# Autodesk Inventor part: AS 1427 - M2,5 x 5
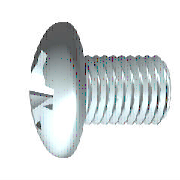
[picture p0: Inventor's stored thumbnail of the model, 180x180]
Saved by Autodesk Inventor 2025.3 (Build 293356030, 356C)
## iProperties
Created: 2024-01
Part Number: AS 1427 - M2,5 x 5
Material: Acciaio, Dolce
Description: Phillips Viti metriche ISO
Document SubType Name: Modeling
Standard: AS 1427
Designer: R5800u
Standards Organization: AS
Language: it-IT
Size Designation: M2,5 x 5
Categories: <MemberInstance><Categories><Category DisplayName="Elementi di fissaggio" InternalName="e4da775c-781d-43d5-af7c-5136215cf5a6" Mnemonic="FSTN"><Category DisplayN
Density: 7.85 g/cm^3
Appearance: Semilucidato
IsCustomPart: 0
Author: R5800u
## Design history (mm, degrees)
body "Solid1"
workplane "Work Plane3"
sketch "Schizzo4"
  geometry: L1 (-9, 0)-(9, 0) reference; L2 (0, -9)-(0, 9) reference; L3 (0, 0)-(6.428, 6.428); L4 (0, 0)-(6.428, -6.428); L5 (0, 0)-(-6.428, 6.428); L6 (0, 0)-(-6.428, -6.428); L7 (0.94, 0.94)-(0, 0.128); L8 (-0.94, 0.94)-(-0.128, 0); L9 (-0.94, -0.94)-(0, -0.128); L10 (0.94, -0.94)-(0.127, 0); L11 (0.94, 0.94)-(0.128, 0); L12 (-0.94, 0.94)-(0, 0.128); L13 (-0.94, -0.94)-(-0.127, 0); L14 (0.94, -0.94)-(0, -0.128); C1 r 2.5 at (0, 0) reference; A1 r 0.128 centre (0, 0) between (0, 0.128) and (-0.128, 0); A2 r 1.33 centre (0, 0) between (0.94, 0.94) and (0.94, -0.94); 1 further point
  constraints: 24 end point, 10 point on line, 7 point on circle, 3 perpendicular, 3 symmetric about line, 2 centre point, 2 coincident, 3 other
  dimensions: "d11" = 0.255 diameter of A1 (= 0.5 x SBR); "d14" = 45 deg angle of L3 L1; "d35" = 0.94045 distance from line of L1 L7.start (= 0.353553 x SDM)
extrude "Taglio a stella" cut sketch "Schizzo4" distance "d12" = 1.75 (= KOH); taper "d13" = -10 deg
sketch "Schizzo2"
  geometry: L1 (-4.344, 0)-(8.565, 0) reference; L2 (0, -4.344)-(0, 8.565) reference; L3 (0, 1.33)-(0, 0); L4 (0, 0)-(1.33, 0); L5 (0, 0)-(6.721, 6.721); L6 (0.255, 1.305)-(0.176, 0.641); L7 (1.305, 0.255)-(0.641, 0.176); L8 (1.305, -0.255)-(0.641, -0.176); L9 (0.255, -1.305)-(0.176, -0.641); L10 (-0.255, 1.305)-(-0.176, 0.641); L11 (-1.305, 0.255)-(-0.641, 0.176); L12 (-0.255, -1.305)-(-0.176, -0.641); L13 (-1.305, -0.255)-(-0.641, -0.176); C1 r 2.5 at (0, 0) reference; A1 r 0.532 centre (0, 0) between (0.532, 0) and (0, 0.532); A2 r 0.184 centre (0.359, 0.62) between (0.176, 0.641) and (0.489, 0.489); A3 r 0.184 centre (0.62, 0.359) between (0.489, 0.489) and (0.641, 0.176); A4 r 1.33 centre (0, 0) between (1.33, 0) and (1.305, 0.255); A5 r 1.33 centre (0, 0) between (0.255, 1.305) and (0, 1.33); A6 r 1.33 centre (0, 0) between (1.305, 0.255) and (0.255, 1.305); A7 r 1.33 centre (0, 0) between (0, -1.33) and (0.255, -1.305); A8 r 1.33 centre (0, 0) between (0.255, -1.305) and (1.305, -0.255); A9 r 1.33 centre (0, 0) between (1.305, -0.255) and (1.33, 0); A10 r 0.184 centre (0.359, -0.62) between (0.489, -0.489) and (0.176, -0.641); A11 r 0.184 centre (0.62, -0.359) between (0.641, -0.176) and (0.489, -0.489); A12 r 0.184 centre (-0.359, 0.62) between (-0.489, 0.489) and (-0.176, 0.641); A13 r 0.184 centre (-0.62, 0.359) between (-0.641, 0.176) and (-0.489, 0.489); A14 r 1.33 centre (0, 0) between (-1.305, 0.255) and (-1.33, 0); A15 r 1.33 centre (0, 0) between (-0.255, 1.305) and (-1.305, 0.255); A16 r 1.33 centre (0, 0) between (0, 1.33) and (-0.255, 1.305); A17 r 1.33 centre (0, 0) between (-1.33, 0) and (-1.305, -0.255); A18 r 1.33 centre (0, 0) between (-1.305, -0.255) and (-0.255, -1.305); A19 r 1.33 centre (0, 0) between (-0.255, -1.305) and (0, -1.33); A20 r 0.184 centre (-0.62, -0.359) between (-0.489, -0.489) and (-0.641, -0.176); A21 r 0.184 centre (-0.359, -0.62) between (-0.176, -0.641) and (-0.489, -0.489); A22 r 0.665 centre (0, 0) between (0.665, 0) and (0, 0.665)
  constraints: 46 point on circle, 25 symmetric about line, 22 centre point, 22 end point, 6 tangent, 4 coincident, 3 collinear, 3 point on line, 1 midpoint, 1 perpendicular, 22 other
  dimensions: "d4" = 45 deg angle of L5 L4; "d5" = 1.064 diameter of A1 (= 0.4 x SDM); "d6" = 2.66 diameter of A6 (= SDM); "d7" = 0.255 distance from line of L6.start L3 (= 0.5 x SBR); "d20" = 1.33 diameter of A22 (= 0.5 x SDM)
extrude "Intaglio" join sketch "Schizzo2" taper "d21" = 5 deg; stored distance "d54" = 10
revolve "Taglio" stored, may be unused: angle "d56" = 90 deg
revolve "Corpo" stored, may be unused: angle "d18" = 90 deg
workplane "Work Plane1"
sketch "Schizzo1"
  geometry: L1 (5, 0)-(5, 1.25); L2 (5, 1.25)-(0.9, 1.25); L3 (3.962, 5.08)-(3.962, 5.08); L4 (-1.75, 0)-(-1.75, 2.5); L5 (-1.521, 1.216)-(-1.229, 1.07); L6 (-1.229, 1.07)-(-0.66, 0); L7 (-0.66, 0)-(5, 0); L8 (-3.421, 0)-(6.403, 0) reference; L9 (0, -1.016)-(0, 6.096) reference; L10 (-1.521, 1.216)-(-1.75, 1.33); L11 (-0.63, 2.5)-(-1.75, 2.5); L12 (-0.63, 2.5)-(0, 2.5); L13 (0, 2.5)-(0, 1.112); L14 (0, 1.112)-(0.624, 1.112); L15 (0.624, 1.112)-(0.9, 1.25); L16 (0.9, 1.25)-(0, 1.25); A1 r 3.35 centre (1.6, 0) between (-0.63, 2.5) and (-1.75, 0)
  constraints: 28 end point, 5 point on line, 4 collinear, 4 point on circle, 3 parallel, 2 perpendicular, 1 centre point, 1 horizontal, 1 tangent
  dimensions: "d1" = 2.5 diameter of L2 L7 (= GD); "d2" = 1.09 distance from line of L6.end L4 (= STI); "d16" = 2.66 diameter of L10.end L7 (= SDM); "d17" = 62 deg angle of L6 L7; "d19" = 26.5 deg angle of L5 L7; "d23" = 5 diameter of L12.end L7 (= KOD); "d24" = 0.01 deg angle of L12 L7 (= KEWI); "d25" = 1.75 distance between parallel lines of L4 L13 (= KOH); "d26" = 3.35 radius of A1 (= KR); "d28" = 2.224 diameter of L14 L7 (= BDM); "d29" = 4.1 distance of L1.end L2.end (= GEL); "d30" = 0.27605 horizontal distance of L14.end L2.end (= GAL); "d31" = 5 distance between parallel lines of L13 L1 (= NLG)
fillet "Raccordo1" dims "d32" = 1 (= RR)
fillet "Raccordo2" dims "d22" = 0.102 (= 0.2 x SBR)
feature "Filettatura" dims "d8" = 4.1 (= GEL), "d9" = 0
chamfer "Smusso1" distance "d36" = 0.27605 (= -0.5 x SPD + 0.5 x GD); stored, may be unused: second distance "d37" = 0.27615 (computed from GUL), angle "d81" = 45 deg
other parameters: "GD" = 2.5 (= NND) [user parameter; used in 2 equation terms], "NLG" = 5 [user parameter; used in 1 equation term], "GEL" = 4.1 [user parameter; used in 2 equation terms], "KOD" = 5 [user parameter; used in 1 equation term], "KOH" = 1.75 [user parameter; used in 3 equation terms], "SDM" = 2.66 [user parameter; used in 5 equation terms], "STI" = 1.09 [user parameter; used in 1 equation term], "SBR" = 0.51 [user parameter; used in 3 equation terms], "KEWI" = 0.01 deg [user parameter; used in 1 equation term], "d3" = -1.75 (= -KOH), "d10" = 0, "KR" = 3.35 [user parameter; used in 1 equation term], "BDM" = 2.224 [user parameter; used in 1 equation term], "GAL" = 0.27605 (= 0.61345 x PTC) [user parameter; used in 1 equation term], "GUL" = 0.27605 (= 0.61345 x PTC) [user parameter; used in 1 equation term], "RR" = 1 [user parameter; used in 1 equation term], "SPD" = 1.94789 (= NND - 1.2269 x PTC) [user parameter; used in 1 equation term], "d82" = 0, "d83" = 0, "PTC" = 0.45 [user parameter; used in 5 equation terms], "THREADDIA" = 2.5 [user parameter; used in 1 equation term], "TOA" = 30 deg [user parameter], "TPU" = 22.22222 (computed from PTC) [user parameter], "NND" = 2.5 [user parameter; used in 2 equation terms], "GD1" = 1.94789 (= THREADDIA - 1.2269 x PTC) [user parameter]
